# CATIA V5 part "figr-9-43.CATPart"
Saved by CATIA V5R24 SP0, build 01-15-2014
Part number: Part1
Bounding box of the stored display mesh (mm): x -60 to 60, y -70.327 to 65.87, z 0 to 125
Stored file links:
  D:\KAVITA\CATIA V5-6R2014 Project_ Kavita\CATIA V5-6R2014_partfiles\Partfiles\c09_catia_v5-6r2014_prt\figr-9-43.CATPart
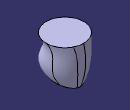
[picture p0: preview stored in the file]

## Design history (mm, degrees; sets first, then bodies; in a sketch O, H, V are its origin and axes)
Set1
  Plane1: type Offset, RefPlane xy-plane, Offset 125
Body1 (main body)
  Sketch1 on xy-plane, origin (0, 0, 0), H (1, 0, 0), V (0, 1, 0)
    ellipse A1 centre (0, 0) semi-axes 50, 30 rotation 270
    point P1 (30, 0)
    coincidence: P1 H, A1 P1
  Sketch2 on Plane1, origin (0, 0, 125), H (1, 0, 0), V (0, 1, 0)
    circle A1 centre (0, 0) radius 60
  Sketch3 on yz-plane, origin (0, 0, 0), H (0, 1, 0), V (0, 0, 1)
    arc A1 centre (-129.6632, 77.2731) radius 195.5761 from (50, 0) to (60, 125) ccw
    point P2 (50, 0)
    point P3 (60, 125)
    reference projected line E1 (-50, 0) -> (50, 0) from edge of Sketch1
    reference projected line E2 (-60, 125) -> (60, 125) from edge of Sketch2
    coincidence: P2 H, P2 E1, P3 E2
  Sketch4 on yz-plane, origin (0, 0, 0), H (0, 1, 0), V (0, 0, 1)
    spline S1 through (-50, 0) (-70, 40) (-50, 100) (-60, 125)
    reference projected line E1 (-60, 125) -> (60, 125) from edge of Sketch2
    reference projected line E2 (-50, 0) -> (50, 0) from edge of Sketch1
    point P1 (-60, 125)
    point P2 (-50, 0)
    coincidence: P1 E1, P2 E2
  Loft1: Sections (Sketch1; Sketch2), Guides (Sketch3; Sketch4)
